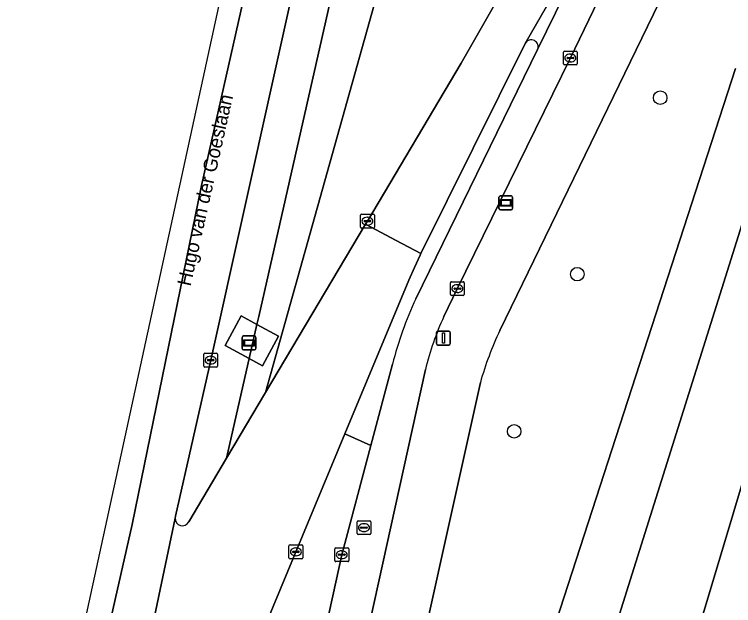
# Model space of a CAD drawing. Extents: x 163043 to 165076, y 382019 to 382874.
# Drawn here: x 163046 to 163098, y 382532.5 to 382575.2 of the extents above; entities that cross this region are included whole.
import ezdxf

# ---------------------------------------------------------------- set-up
doc = ezdxf.new("R2010")
doc.units = 0
for name, color, linetype in [('IMGEO_Berm_groen', 7, 'Continuous'), ('IMGEO_Boom', 7, 'Continuous'), ('IMGEO_Fietspad_open', 7, 'Continuous'), ('IMGEO_Kolk', 7, 'Continuous'), ('IMGEO_Lichtmast', 7, 'Continuous'), ('IMGEO_Oever', 7, 'Continuous'), ('IMGEO_Openbare_ruimte_label', 7, 'Continuous'), ('IMGEO_Reclamebord', 7, 'Continuous'), ('IMGEO_Rijbaan_lokaal_gesloten', 7, 'Continuous'), ('IMGEO_Rijbaan_lokaal_open', 7, 'Continuous'), ('IMGEO_Rijbaan_regionaal_gesloten', 7, 'Continuous'), ('IMGEO_Rioolput', 7, 'Continuous'), ('IMGEO_Verkeerseiland_open', 7, 'Continuous'), ('IMGEO_Voetpad_open', 7, 'Continuous'), ('IMGEO_Waterloop', 7, 'Continuous'), ('IMGEO_Wegwijzer', 7, 'Continuous')]:
    doc.layers.add(name, color=color, linetype=linetype)

msp = doc.modelspace()

# ---------------------------------------------------------------- linework, layer by layer
at = {"layer": 'IMGEO_Berm_groen'}
for points in [[(163092.443, 382688.126), (163092.16, 382686.861), (163091.729, 382686.98), (163091.413, 382685.819), (163090.33, 382686.051), (163060.202, 382550.237), (163057.66, 382538.947), (163057.634, 382538.822)], [(163100.832, 382683.6), (163098.443, 382676.291), (163089.933, 382645.473), (163080.796, 382607.304), (163064.17, 382547.891), (163071.394, 382560.063), (163071.521, 382560.278), (163071.529, 382560.291), (163078.286, 382571.691), (163080.888, 382576.25), (163091.395, 382595.056)], [(163058.622, 382538.547), (163061.352, 382543.143), (163062.985, 382550.353), (163061.239, 382551.304), (163062.402, 382553.439), (163063.543, 382552.818), (163063.671, 382553.383), (163092.671, 382681.431)], [(163111.94, 382582.815), (163110.751, 382583.398), (163109.184, 382579.138), (163108.124, 382576.448), (163105.45, 382577.479), (163106.479, 382580.107), (163108.054, 382584.721), (163101.618, 382587.878), (163101.423, 382587.972), (163098.995, 382589.137), (163097.844, 382586.779), (163095.46, 382582.022), (163081.09, 382552.378)], [(163079.41, 382513.579), (163098.094, 382571.31)], [(163079.679, 382548.626), (163073.606, 382521.183), (163070.492, 382506.972), (163068.968, 382500), (163065.947, 382486.176)], [(163067.191, 382524.864), (163069.665, 382536.151), (163071.757, 382544.071), (163069.894, 382544.912), (163058.472, 382517.403), (163057.328, 382514.544), (163053.768, 382506.009)]]:
    msp.add_lwpolyline(points, dxfattribs=at)
msp.add_lwpolyline([(163089.933, 382645.473), (163098.443, 382676.291), (163100.832, 382683.6), (163093.932, 382685.896), (163093.759, 382685.284), (163092.671, 382681.431), (163063.671, 382553.383), (163063.543, 382552.818), (163065.11, 382551.964), (163063.947, 382549.829), (163062.985, 382550.353), (163061.352, 382543.143), (163064.17, 382547.891), (163080.796, 382607.304)], close=True, dxfattribs=at)
for centre, radius, start, end in [((163101.675, 382542.495), 22.834, 154.3548, 164.426), ((163058.154, 382538.778), 0.522, 175.1314, 333.7606)]:
    msp.add_arc(centre, radius, start, end, dxfattribs=at)
at = {"layer": 'IMGEO_Boom'}
for centre in [(163092.668, 382569.203), (163086.678, 382556.45), (163082.117, 382545.088)]:
    msp.add_circle(centre, 0.489, dxfattribs=at)
at = {"layer": 'IMGEO_Fietspad_open'}
for points in [[(163077.04, 382553.381), (163078.013, 382555.397), (163086.165, 382572.05), (163091.883, 382583.941), (163092.391, 382584.969), (163090.329, 382586.006), (163083.814, 382572.678), (163075.006, 382554.656)], [(163073.328, 382549.944), (163071.757, 382544.071), (163069.665, 382536.151), (163067.191, 382524.864), (163064.403, 382512.197), (163062.59, 382503.776), (163061.753, 382500), (163060.171, 382492.863)], [(163063.356, 382493.212), (163064.83, 382500), (163067.388, 382511.786), (163070.131, 382524.198), (163075.706, 382549.562)]]:
    msp.add_lwpolyline(points, dxfattribs=at)
for centre, radius, start, end in [((163100.06, 382543.079), 27.599, 155.1995, 165.5977), ((163097.064, 382544.244), 22.01, 155.4726, 166.0182)]:
    msp.add_arc(centre, radius, start, end, dxfattribs=at)
at = {"layer": 'IMGEO_Kolk'}
for p, q in [((163085.677, 382571.649), (163085.677, 382572.501)), ((163085.752, 382572.575), (163086.604, 382572.575)), ((163086.165, 382572.355), (163086.19, 382572.355)), ((163086.678, 382572.501), (163086.678, 382571.649)), ((163085.936, 382572.069), (163085.936, 382572.081)), ((163086.374, 382572.032), (163085.976, 382572.032)), ((163085.979, 382572.118), (163086.377, 382572.118)), ((163086.188, 382571.795), (163086.163, 382571.795)), ((163086.42, 382572.081), (163086.42, 382572.069)), ((163086.604, 382571.575), (163085.752, 382571.575)), ((163071.095, 382560.78), (163071.947, 382560.78)), ((163071.02, 382559.854), (163071.02, 382560.706)), ((163071.279, 382560.274), (163071.279, 382560.286)), ((163071.717, 382560.237), (163071.319, 382560.237)), ((163071.322, 382560.323), (163071.72, 382560.323)), ((163071.508, 382560.56), (163071.533, 382560.56)), ((163071.763, 382560.286), (163071.763, 382560.274)), ((163072.021, 382560.706), (163072.021, 382559.854)), ((163071.947, 382559.78), (163071.095, 382559.78)), ((163071.531, 382560), (163071.506, 382560)), ((163077.517, 382554.98), (163077.517, 382555.832)), ((163077.592, 382555.906), (163078.444, 382555.906)), ((163078.005, 382555.686), (163078.03, 382555.686)), ((163078.518, 382555.832), (163078.518, 382554.98)), ((163077.776, 382555.4), (163077.776, 382555.412)), ((163078.214, 382555.363), (163077.816, 382555.363)), ((163077.819, 382555.449), (163078.217, 382555.449)), ((163078.028, 382555.126), (163078.003, 382555.126)), ((163078.26, 382555.412), (163078.26, 382555.4)), ((163078.444, 382554.906), (163077.592, 382554.906)), ((163059.702, 382549.81), (163059.702, 382550.662)), ((163059.777, 382550.736), (163060.629, 382550.736)), ((163060.19, 382550.516), (163060.215, 382550.516)), ((163060.703, 382550.662), (163060.703, 382549.81)), ((163059.961, 382550.23), (163059.961, 382550.242)), ((163060.399, 382550.193), (163060.001, 382550.193)), ((163060.004, 382550.279), (163060.402, 382550.279)), ((163060.213, 382549.956), (163060.188, 382549.956)), ((163060.445, 382550.242), (163060.445, 382550.23)), ((163060.629, 382549.736), (163059.777, 382549.736)), ((163065.93, 382536.881), (163066.782, 382536.881)), ((163065.855, 382535.955), (163065.855, 382536.807)), ((163066.114, 382536.375), (163066.114, 382536.387)), ((163066.552, 382536.338), (163066.154, 382536.338)), ((163066.157, 382536.424), (163066.555, 382536.424)), ((163066.343, 382536.661), (163066.368, 382536.661)), ((163066.598, 382536.387), (163066.598, 382536.375)), ((163066.856, 382536.807), (163066.856, 382535.955)), ((163069.168, 382535.743), (163069.168, 382536.595)), ((163069.243, 382536.669), (163070.095, 382536.669)), ((163069.656, 382536.449), (163069.681, 382536.449)), ((163070.169, 382536.595), (163070.169, 382535.743)), ((163066.782, 382535.881), (163065.93, 382535.881)), ((163066.366, 382536.101), (163066.341, 382536.101)), ((163069.427, 382536.163), (163069.427, 382536.175)), ((163069.865, 382536.126), (163069.467, 382536.126)), ((163069.47, 382536.212), (163069.868, 382536.212)), ((163069.679, 382535.889), (163069.654, 382535.889)), ((163069.911, 382536.175), (163069.911, 382536.163)), ((163070.095, 382535.669), (163069.243, 382535.669))]:
    msp.add_line(p, q, dxfattribs=at)
for points in [[(163085.677, 382571.649), (163085.677, 382572.501)], [(163085.752, 382572.575), (163086.604, 382572.575)], [(163086.678, 382572.501), (163086.678, 382571.649)], [(163086.604, 382571.575), (163085.752, 382571.575)], [(163071.095, 382560.78), (163071.947, 382560.78)], [(163071.02, 382559.854), (163071.02, 382560.706)], [(163072.021, 382560.706), (163072.021, 382559.854)], [(163071.947, 382559.78), (163071.095, 382559.78)], [(163077.517, 382554.98), (163077.517, 382555.832)], [(163077.592, 382555.906), (163078.444, 382555.906)], [(163078.518, 382555.832), (163078.518, 382554.98)], [(163078.444, 382554.906), (163077.592, 382554.906)], [(163059.702, 382549.81), (163059.702, 382550.662)], [(163059.777, 382550.736), (163060.629, 382550.736)], [(163060.703, 382550.662), (163060.703, 382549.81)], [(163060.629, 382549.736), (163059.777, 382549.736)], [(163065.93, 382536.881), (163066.782, 382536.881)], [(163065.855, 382535.955), (163065.855, 382536.807)], [(163066.856, 382536.807), (163066.856, 382535.955)], [(163069.168, 382535.743), (163069.168, 382536.595)], [(163069.243, 382536.669), (163070.095, 382536.669)], [(163070.169, 382536.595), (163070.169, 382535.743)], [(163066.782, 382535.881), (163065.93, 382535.881)], [(163070.095, 382535.669), (163069.243, 382535.669)]]:
    msp.add_lwpolyline(points, dxfattribs=at)
for centre, radius, start, end in [((163085.754, 382572.499), 0.0765, 91.552, 178.448), ((163085.754, 382572.499), 0.0765, 91.552, 178.448), ((163086.602, 382572.499), 0.0765, 1.552, 88.448), ((163086.602, 382572.499), 0.0765, 1.552, 88.448), ((163085.754, 382571.651), 0.0765, 181.552, 268.448), ((163085.754, 382571.651), 0.0765, 181.552, 268.448), ((163085.976, 382572.078), 0.0403, 85.8775, 175.7526), ((163085.973, 382572.068), 0.0366, 178.938, 274.7102), ((163086.377, 382572.075), 0.043, 264.8664, 352.4533), ((163086.381, 382572.08), 0.0386, 1.7309, 96.639), ((163086.602, 382571.651), 0.0765, 271.552, 358.448), ((163086.602, 382571.651), 0.0765, 271.552, 358.448), ((163071.097, 382560.704), 0.0765, 91.552, 178.448), ((163071.097, 382560.704), 0.0765, 91.552, 178.448), ((163071.945, 382560.704), 0.0765, 1.552, 88.448), ((163071.945, 382560.704), 0.0765, 1.552, 88.448), ((163071.319, 382560.283), 0.0403, 85.8775, 175.7526), ((163071.316, 382560.273), 0.0366, 178.938, 274.7102), ((163071.72, 382560.28), 0.043, 264.8664, 352.4533), ((163071.724, 382560.285), 0.0386, 1.7309, 96.639), ((163071.097, 382559.856), 0.0765, 181.552, 268.448), ((163071.097, 382559.856), 0.0765, 181.552, 268.448), ((163071.945, 382559.856), 0.0765, 271.552, 358.448), ((163071.945, 382559.856), 0.0765, 271.552, 358.448), ((163077.594, 382555.83), 0.0765, 91.552, 178.448), ((163077.594, 382555.83), 0.0765, 91.552, 178.448), ((163078.442, 382555.83), 0.0765, 1.552, 88.448), ((163078.442, 382555.83), 0.0765, 1.552, 88.448), ((163077.816, 382555.409), 0.0403, 85.8775, 175.7526), ((163077.813, 382555.399), 0.0366, 178.938, 274.7102), ((163078.217, 382555.406), 0.043, 264.8664, 352.4533), ((163078.221, 382555.411), 0.0386, 1.7309, 96.639), ((163077.594, 382554.982), 0.0765, 181.552, 268.448), ((163077.594, 382554.982), 0.0765, 181.552, 268.448), ((163078.442, 382554.982), 0.0765, 271.552, 358.448), ((163078.442, 382554.982), 0.0765, 271.552, 358.448), ((163059.779, 382550.66), 0.0765, 91.552, 178.448), ((163059.779, 382550.66), 0.0765, 91.552, 178.448), ((163060.627, 382550.66), 0.0765, 1.552, 88.448), ((163060.627, 382550.66), 0.0765, 1.552, 88.448), ((163060.001, 382550.239), 0.0403, 85.8775, 175.7526), ((163059.998, 382550.229), 0.0366, 178.938, 274.7102), ((163060.402, 382550.236), 0.043, 264.8664, 352.4533), ((163060.406, 382550.241), 0.0386, 1.7309, 96.639), ((163059.779, 382549.812), 0.0765, 181.552, 268.448), ((163059.779, 382549.812), 0.0765, 181.552, 268.448), ((163060.627, 382549.812), 0.0765, 271.552, 358.448), ((163060.627, 382549.812), 0.0765, 271.552, 358.448), ((163065.932, 382536.805), 0.0765, 91.552, 178.448), ((163065.932, 382536.805), 0.0765, 91.552, 178.448), ((163066.78, 382536.805), 0.0765, 1.552, 88.448), ((163066.78, 382536.805), 0.0765, 1.552, 88.448), ((163066.154, 382536.384), 0.0403, 85.8775, 175.7526), ((163066.151, 382536.374), 0.0366, 178.938, 274.7102), ((163066.555, 382536.381), 0.043, 264.8664, 352.4533), ((163066.559, 382536.386), 0.0386, 1.7309, 96.639), ((163069.245, 382536.593), 0.0765, 91.552, 178.448), ((163069.245, 382536.593), 0.0765, 91.552, 178.448), ((163070.093, 382536.593), 0.0765, 1.552, 88.448), ((163070.093, 382536.593), 0.0765, 1.552, 88.448), ((163065.932, 382535.957), 0.0765, 181.552, 268.448), ((163065.932, 382535.957), 0.0765, 181.552, 268.448), ((163066.78, 382535.957), 0.0765, 271.552, 358.448), ((163066.78, 382535.957), 0.0765, 271.552, 358.448), ((163069.467, 382536.172), 0.0403, 85.8775, 175.7526), ((163069.464, 382536.162), 0.0366, 178.938, 274.7102), ((163069.868, 382536.169), 0.043, 264.8664, 352.4533), ((163069.872, 382536.174), 0.0386, 1.7309, 96.639), ((163069.245, 382535.745), 0.0765, 181.552, 268.448), ((163069.245, 382535.745), 0.0765, 181.552, 268.448), ((163070.093, 382535.745), 0.0765, 271.552, 358.448), ((163070.093, 382535.745), 0.0765, 271.552, 358.448)]:
    msp.add_arc(centre, radius, start, end, dxfattribs=at)
for centre, major_axis, ratio, start_param, end_param in [((163086.164, 382572.075), (-0.387, 0.002), 0.722429, 4.712389, 7.853982), ((163086.189, 382572.075), (-0.39, 0.002), 0.717154, 1.570796, 4.712389), ((163071.507, 382560.28), (-0.387, 0.002), 0.722429, 4.712389, 7.853982), ((163071.532, 382560.28), (-0.39, 0.002), 0.717154, 1.570796, 4.712389), ((163078.004, 382555.406), (-0.387, 0.002), 0.722429, 4.712389, 7.853982), ((163078.029, 382555.406), (-0.39, 0.002), 0.717154, 1.570796, 4.712389), ((163060.189, 382550.236), (-0.387, 0.002), 0.722429, 4.712389, 7.853982), ((163060.214, 382550.236), (-0.39, 0.002), 0.717154, 1.570796, 4.712389), ((163066.342, 382536.381), (-0.387, 0.002), 0.722429, 4.712389, 7.853982), ((163066.367, 382536.381), (-0.39, 0.002), 0.717154, 1.570796, 4.712389), ((163069.655, 382536.169), (-0.387, 0.002), 0.722429, 4.712389, 7.853982), ((163069.68, 382536.169), (-0.39, 0.002), 0.717154, 1.570796, 4.712389)]:
    msp.add_ellipse(centre, major_axis=major_axis, ratio=ratio, start_param=start_param, end_param=end_param, dxfattribs=at)
at = {"layer": 'IMGEO_Lichtmast'}
for p, q in [((163076.517, 382551.429), (163076.517, 382552.229)), ((163076.517, 382552.229), (163076.517, 382551.429)), ((163076.617, 382552.329), (163077.407, 382552.329)), ((163077.407, 382552.329), (163076.617, 382552.329)), ((163077.507, 382552.229), (163077.507, 382551.429)), ((163077.507, 382551.429), (163077.507, 382552.229)), ((163077.407, 382551.329), (163076.617, 382551.329)), ((163076.617, 382551.329), (163077.407, 382551.329))]:
    msp.add_line(p, q, dxfattribs=at)
msp.add_lwpolyline([(163076.937, 382552.204), (163077.087, 382552.204), (163077.087, 382551.454), (163076.937, 382551.454), (163076.937, 382552.204)], dxfattribs=at)
for centre, start, end in [((163076.617, 382552.229), 90, 180), ((163076.617, 382552.229), 90, 180), ((163077.407, 382552.229), 0, 90), ((163077.407, 382552.229), 360, 90), ((163076.617, 382551.429), 180, 270), ((163076.617, 382551.429), 180, 270), ((163077.407, 382551.429), 270, 0), ((163077.407, 382551.429), 270, 0)]:
    msp.add_arc(centre, 0.1, start, end, dxfattribs=at)
at = {"layer": 'IMGEO_Oever'}
msp.add_lwpolyline([(163089.325, 382510.365), (163090.472, 382507.307), (163091.661, 382504.207), (163092, 382502.254), (163091.024, 382500.938), (163089.198, 382499.919), (163087.244, 382499.834), (163085.376, 382500.641), (163084.272, 382503.358), (163083.253, 382511.256), (163101.469, 382569.303), (163103.89, 382571.936), (163105.631, 382571.341), (163106.65, 382568.241)], close=True, dxfattribs=at)
msp.add_lwpolyline([(163098.094, 382571.31), (163079.41, 382513.579)], dxfattribs=at)
at = {"layer": 'IMGEO_Reclamebord'}
for p, q in [((163062.567, 382551.981), (163063.357, 382551.981)), ((163063.357, 382551.981), (163062.567, 382551.981)), ((163062.467, 382551.081), (163062.467, 382551.881)), ((163062.467, 382551.881), (163062.467, 382551.081)), ((163063.457, 382551.881), (163063.457, 382551.081)), ((163063.457, 382551.081), (163063.457, 382551.881)), ((163063.357, 382550.981), (163062.567, 382550.981)), ((163062.567, 382550.981), (163063.357, 382550.981))]:
    msp.add_line(p, q, dxfattribs=at)
for points in [[(163062.568, 382551.713), (163063.356, 382551.713), (163063.356, 382551.249), (163062.568, 382551.249), (163062.568, 382551.713)], [(163062.633, 382551.648), (163062.633, 382551.314), (163063.291, 382551.314), (163063.291, 382551.648), (163062.633, 382551.648)]]:
    msp.add_lwpolyline(points, dxfattribs=at)
for centre, start, end in [((163062.567, 382551.881), 90, 180), ((163062.567, 382551.881), 90, 180), ((163063.357, 382551.881), 0, 90), ((163063.357, 382551.881), 360, 90), ((163062.567, 382551.081), 180, 270), ((163062.567, 382551.081), 180, 270), ((163063.357, 382551.081), 270, 0), ((163063.357, 382551.081), 270, 0)]:
    msp.add_arc(centre, 0.1, start, end, dxfattribs=at)
at = {"layer": 'IMGEO_Rijbaan_lokaal_gesloten'}
for points in [[(163069.894, 382544.912), (163074.517, 382556.019), (163074.917, 382556.943), (163075.337, 382557.831), (163075.39, 382557.937), (163073.608, 382558.885), (163071.394, 382560.063), (163064.17, 382547.891), (163061.352, 382543.143), (163058.622, 382538.547)], [(163053.768, 382506.009), (163057.328, 382514.544), (163058.472, 382517.403), (163069.894, 382544.912)], [(163057.634, 382538.822), (163056.043, 382531.239)]]:
    msp.add_lwpolyline(points, dxfattribs=at)
msp.add_arc((163058.154, 382538.778), 0.522, 175.1314, 333.7606, dxfattribs=at)
at = {"layer": 'IMGEO_Rijbaan_lokaal_open'}
msp.add_lwpolyline([(163105.234, 382623.709), (163105.152, 382621.702), (163105.112, 382621.316), (163104.983, 382620.922), (163099.17, 382609.144), (163098.994, 382608.778), (163091.471, 382595.168), (163091.395, 382595.056), (163080.888, 382576.25), (163078.286, 382571.691), (163071.529, 382560.291), (163071.521, 382560.278), (163071.394, 382560.063), (163073.608, 382558.885), (163075.39, 382557.937), (163075.414, 382557.986), (163082.917, 382573.134), (163090.329, 382586.006), (163108.703, 382621.111), (163124.332, 382653.2)], dxfattribs=at)
at = {"layer": 'IMGEO_Rijbaan_regionaal_gesloten'}
for points in [[(163046.024, 382495.301), (163047.305, 382495.062), (163048.819, 382506.093), (163052.083, 382527.523), (163054.53, 382538.366), (163059.54, 382562.869), (163067.335, 382597.474), (163067.523, 382598.31), (163074.981, 382632.119), (163086.605, 382686.214), (163089.029, 382696.676), (163088.769, 382696.731), (163086.873, 382697.143), (163069.23, 382614.776), (163050.516, 382528.634), (163046.024, 382495.301)], [(163056.043, 382531.239), (163057.634, 382538.822), (163057.66, 382538.947), (163060.202, 382550.237), (163090.33, 382686.051), (163092.214, 382694.532), (163092.525, 382695.935), (163089.029, 382696.676), (163086.605, 382686.214), (163074.981, 382632.119), (163067.523, 382598.31), (163067.335, 382597.474), (163059.54, 382562.869), (163054.53, 382538.366), (163052.083, 382527.523), (163048.819, 382506.093), (163047.305, 382495.062), (163050.809, 382494.33), (163051.097, 382497.32), (163051.24, 382498.35), (163051.438, 382500)]]:
    msp.add_lwpolyline(points, dxfattribs=at)
at = {"layer": 'IMGEO_Rioolput'}
for p, q in [((163070.771, 382537.702), (163070.771, 382538.554)), ((163070.846, 382538.628), (163071.698, 382538.628)), ((163071.259, 382538.408), (163071.284, 382538.408)), ((163071.772, 382538.554), (163071.772, 382537.702)), ((163071.03, 382538.122), (163071.03, 382538.134)), ((163071.468, 382538.085), (163071.07, 382538.085)), ((163071.073, 382538.171), (163071.471, 382538.171)), ((163071.514, 382538.134), (163071.514, 382538.122)), ((163071.698, 382537.628), (163070.846, 382537.628)), ((163071.282, 382537.848), (163071.257, 382537.848))]:
    msp.add_line(p, q, dxfattribs=at)
for points in [[(163070.771, 382537.702), (163070.771, 382538.554)], [(163070.846, 382538.628), (163071.698, 382538.628)], [(163071.772, 382538.554), (163071.772, 382537.702)], [(163071.698, 382537.628), (163070.846, 382537.628)]]:
    msp.add_lwpolyline(points, dxfattribs=at)
for centre, radius, start, end in [((163070.848, 382538.552), 0.0765, 91.552, 178.448), ((163070.848, 382538.552), 0.0765, 91.552, 178.448), ((163071.696, 382538.552), 0.0765, 1.552, 88.448), ((163071.696, 382538.552), 0.0765, 1.552, 88.448), ((163071.07, 382538.131), 0.0403, 85.8775, 175.7526), ((163071.067, 382538.121), 0.0366, 178.938, 274.7102), ((163071.471, 382538.128), 0.043, 264.8664, 352.4533), ((163071.475, 382538.133), 0.0386, 1.7309, 96.639), ((163070.848, 382537.704), 0.0765, 181.552, 268.448), ((163070.848, 382537.704), 0.0765, 181.552, 268.448), ((163071.696, 382537.704), 0.0765, 271.552, 358.448), ((163071.696, 382537.704), 0.0765, 271.552, 358.448)]:
    msp.add_arc(centre, radius, start, end, dxfattribs=at)
for centre, major_axis, ratio, start_param, end_param in [((163071.258, 382538.128), (-0.387, 0.002), 0.722429, 4.712389, 7.853982), ((163071.283, 382538.128), (-0.39, 0.002), 0.717154, 1.570796, 4.712389)]:
    msp.add_ellipse(centre, major_axis=major_axis, ratio=ratio, start_param=start_param, end_param=end_param, dxfattribs=at)
at = {"layer": 'IMGEO_Verkeerseiland_open'}
for points in [[(163083.814, 382572.678), (163090.329, 382586.006), (163082.917, 382573.134)], [(163082.917, 382573.134), (163075.414, 382557.986), (163075.39, 382557.937), (163075.337, 382557.831), (163074.917, 382556.943), (163074.517, 382556.019), (163069.894, 382544.912), (163071.757, 382544.071), (163073.328, 382549.944)], [(163075.006, 382554.656), (163083.814, 382572.678)]]:
    msp.add_lwpolyline(points, dxfattribs=at)
for centre, radius, start, end in [((163083.353, 382572.881), 0.504, 336.2724, 149.8336), ((163083.353, 382572.881), 0.504, 336.2724, 149.8336), ((163100.06, 382543.079), 27.599, 155.1995, 165.5977)]:
    msp.add_arc(centre, radius, start, end, dxfattribs=at)
at = {"layer": 'IMGEO_Voetpad_open'}
for points in [[(163081.09, 382552.378), (163095.46, 382582.022), (163097.844, 382586.779), (163094.208, 382588.647), (163092.391, 382584.969), (163091.883, 382583.941), (163086.165, 382572.05), (163078.013, 382555.397), (163077.04, 382553.381)], [(163075.706, 382549.562), (163070.131, 382524.198), (163067.388, 382511.786), (163064.83, 382500), (163063.356, 382493.212)], [(163065.947, 382486.176), (163068.968, 382500), (163070.492, 382506.972), (163073.606, 382521.183), (163079.679, 382548.626)]]:
    msp.add_lwpolyline(points, dxfattribs=at)
for points in [[(163062.402, 382553.439), (163061.239, 382551.304), (163062.985, 382550.353), (163063.543, 382552.818)], [(163063.947, 382549.829), (163065.11, 382551.964), (163063.543, 382552.818), (163062.985, 382550.353)]]:
    msp.add_lwpolyline(points, close=True, dxfattribs=at)
for centre, radius, start, end in [((163097.064, 382544.244), 22.01, 155.4726, 166.0182), ((163101.675, 382542.495), 22.834, 154.3548, 164.426)]:
    msp.add_arc(centre, radius, start, end, dxfattribs=at)
at = {"layer": 'IMGEO_Waterloop'}
msp.add_lwpolyline([(163084.272, 382503.358), (163085.376, 382500.641), (163087.244, 382499.834), (163089.198, 382499.919), (163091.024, 382500.938), (163092, 382502.254), (163091.661, 382504.207), (163090.472, 382507.307), (163089.325, 382510.365), (163106.65, 382568.241), (163105.631, 382571.341), (163103.89, 382571.936), (163101.469, 382569.303), (163083.253, 382511.256)], close=True, dxfattribs=at)
at = {"layer": 'IMGEO_Wegwijzer'}
for p, q in [((163081.021, 382561.204), (163081.021, 382562.004)), ((163081.021, 382562.004), (163081.021, 382561.204)), ((163081.121, 382562.104), (163081.911, 382562.104)), ((163081.911, 382562.104), (163081.121, 382562.104)), ((163082.011, 382562.004), (163082.011, 382561.204)), ((163082.011, 382561.204), (163082.011, 382562.004)), ((163081.911, 382561.104), (163081.121, 382561.104)), ((163081.121, 382561.104), (163081.911, 382561.104))]:
    msp.add_line(p, q, dxfattribs=at)
for points in [[(163081.122, 382561.836), (163081.91, 382561.836), (163081.91, 382561.372), (163081.122, 382561.372), (163081.122, 382561.836)], [(163081.187, 382561.771), (163081.187, 382561.437), (163081.845, 382561.437), (163081.845, 382561.771), (163081.187, 382561.771)]]:
    msp.add_lwpolyline(points, dxfattribs=at)
for centre, start, end in [((163081.121, 382562.004), 90, 180), ((163081.121, 382562.004), 90, 180), ((163081.911, 382562.004), 0, 90), ((163081.911, 382562.004), 360, 90), ((163081.121, 382561.204), 180, 270), ((163081.121, 382561.204), 180, 270), ((163081.911, 382561.204), 270, 0), ((163081.911, 382561.204), 270, 0)]:
    msp.add_arc(centre, 0.1, start, end, dxfattribs=at)

# ---------------------------------------------------------------- texts
at = {"layer": 'IMGEO_Openbare_ruimte_label'}
msp.add_text('Hugo van der Goeslaan', height=1, rotation=77.409, dxfattribs=at).set_placement((163058.744, 382555.532))

doc.saveas('drawing.dxf')
